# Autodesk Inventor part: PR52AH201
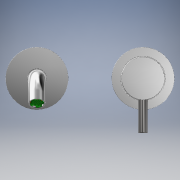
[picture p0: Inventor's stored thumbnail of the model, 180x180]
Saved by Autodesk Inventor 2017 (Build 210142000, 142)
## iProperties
Created: 2021-04
Part Number: PR52AH201
Material: Generico
Document SubType Name: Modeling
Designer: PIZZERA
Density: 1 g/cm^3
Appearance: Default
Author: PIZZERA
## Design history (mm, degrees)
feature "Base2"
node "Solido1"
node "Solido3"
